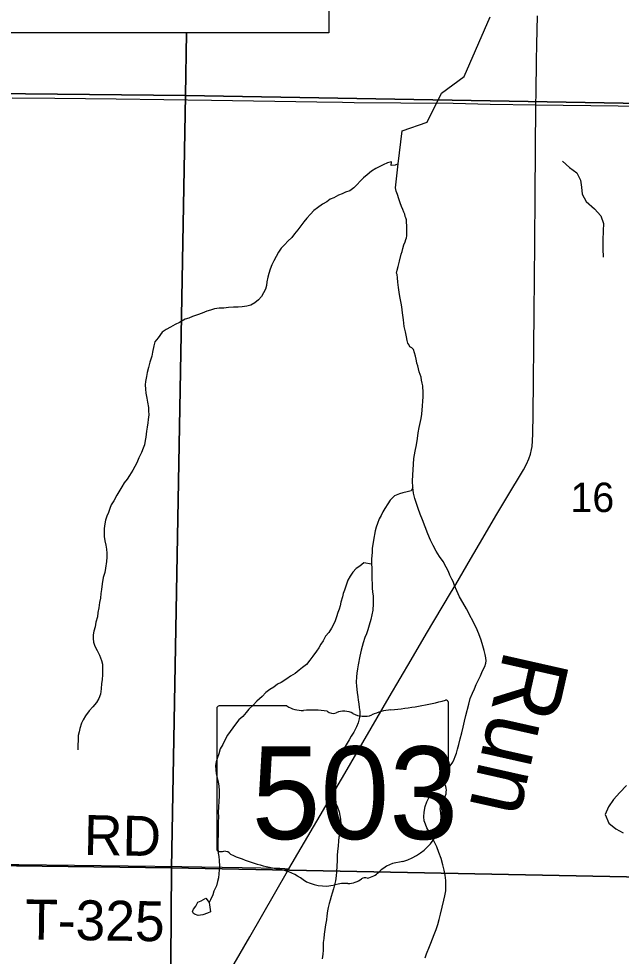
# Model space of a CAD drawing. Extents: x -8.8 to 41.4, y 0 to 34.6.
# Drawn here: x 7.113 to 7.971, y 15.304 to 16.638 of the extents above; entities that cross this region are included whole.
import ezdxf

# ---------------------------------------------------------------- set-up
doc = ezdxf.new("R2010")
doc.units = 0
for name, color, linetype in [('GM_X_City_Street', 7, 'Continuous'), ('GM_X_Corporation', 7, 'Continuous'), ('GM_X_County_Road', 7, 'Continuous'), ('GM_X_Minor_River', 7, 'Continuous'), ('GM_X_Minor_River_Text', 7, 'Continuous'), ('GM_X_Section_Text', 7, 'Continuous'), ('GM_X_State_Route', 7, 'Continuous'), ('GM_X_Township_Road', 7, 'Continuous'), ('GM_X_Township_Text', 7, 'Continuous'), ('GM_X_Unincorporated_Location', 7, 'Continuous'), ('SH_Data', 7, 'Continuous')]:
    doc.layers.add(name, color=color, linetype=linetype)

msp = doc.modelspace()

# ---------------------------------------------------------------- linework, layer by layer
at = {"layer": 'GM_X_City_Street'}
for p, q in [((7.4951, 15.6598), (7.3986, 15.6598)), ((7.725, 15.5601), (7.725, 15.6648)), ((7.3954, 15.6564), (7.3954, 15.4563)), ((7.7249, 15.5601), (7.725, 15.5601))]:
    msp.add_line(p, q, dxfattribs=at)
for centre, major_axis, start_param, end_param in [((7.3992, 15.6568), (0.00382, 0), 1.712693, 3.28349), ((7.5181, 15.683), (0.037, 0), 4.042523, 4.731795), ((7.6076, 15.9326), (0.3495, 0), 4.814394, 5.042369), ((7.7213, 15.6652), (0.00367, 0), 6.141152, 7.989035), ((7.5304, 15.5475), (0.133, 0), 1.404758, 1.657858), ((7.5606, 15.6578), (0.0107, 0), 3.836095, 5.185415), ((7.5763, 15.6347), (0.0222, 0), 0.950623, 2.079405), ((7.6049, 15.6664), (0.0267, 0), 4.081561, 5.145723), ((7.6521, 15.5987), (0.0703, 0), 1.699011, 2.107814), ((7.7241, 15.5524), (0.00568, 0), 1.883978, 3.671073), ((7.721, 15.5597), (0.00393, 0), 5.05454, 6.418171), ((7.688, 15.5392), (0.0341, 0), 5.934695, 6.695948), ((7.7381, 15.5163), (0.0248, 0), 2.387724, 3.262537), ((7.6271, 15.503), (0.0874, 0), 5.101752, 6.440018), ((7.3992, 15.4558), (0.00385, 0), 3.00124, 4.508301), ((7.3998, 15.4763), (0.0294, 0), 4.665946, 4.897461), ((7.4058, 15.4447), (0.0106, 0), 0.519207, 1.627899), ((7.5396, 15.6245), (0.2524, 0), 4.195997, 4.488961), ((7.664, 15.4001), (0.0479, 0), 1.647645, 2.488434), ((7.4644, 15.3663), (0.079, 0), 0.823519, 1.323587), ((7.6033, 15.4369), (0.0282, 0), 4.937069, 5.64225), ((7.5498, 15.4437), (0.0501, 0), 4.026481, 4.996735), ((7.5787, 15.3745), (0.0412, 0), 1.495662, 1.94098), ((7.5824, 15.4287), (0.0267, 0), 4.691044, 5.507374), ((7.6065, 15.4093), (0.00752, 0), 1.147584, 2.315152)]:
    msp.add_ellipse(centre, major_axis=major_axis, ratio=0.8, start_param=start_param, end_param=end_param, dxfattribs=at)
at = {"layer": 'GM_X_Corporation'}
for points in [[(7.3578, 17.0515), (7.3641, 17.5315), (8.3581, 17.5144), (8.3533, 16.5107), (7.351, 16.5283), (7.3522, 16.6176)], [(7.3522, 16.6176), (7.351, 16.5283), (6.3489, 16.539), (6.3498, 16.6176)]]:
    msp.add_lwpolyline(points, dxfattribs=at)
for points in [[(6.3489, 16.539), (7.351, 16.5283), (7.3307, 15.4293), (6.3374, 15.4422)], [(7.351, 16.5283), (8.3533, 16.5107), (8.3386, 15.4097), (7.3307, 15.4293)], [(6.3374, 15.4422), (7.3307, 15.4293), (7.3236, 14.4245), (6.336, 14.4395)], [(7.3307, 15.4293), (8.3386, 15.4097), (8.3298, 14.411), (7.3236, 14.4245)]]:
    msp.add_lwpolyline(points, close=True, dxfattribs=at)
at = {"layer": 'GM_X_County_Road'}
for points in [[(7.1041, 16.5251), (7.1649, 16.5244), (7.2519, 16.5234), (7.3879, 16.5217), (7.5376, 16.5191), (7.5743, 16.5187), (7.5911, 16.5184), (7.6574, 16.5178), (7.7319, 16.5174), (7.7846, 16.516), (7.8496, 16.5151)], [(7.8496, 16.5151), (8.084, 16.5124), (8.3525, 16.5093), (8.5865, 16.5068), (8.7909, 16.5044), (8.9, 16.5027)]]:
    msp.add_lwpolyline(points, dxfattribs=at)
at = {"layer": 'GM_X_Minor_River'}
for points in [[(7.6536, 16.431), (7.659, 16.4782), (7.695, 16.4906), (7.7154, 16.5317), (7.7473, 16.5553), (7.7844, 16.6404)], [(7.6536, 16.431), (7.6493, 16.4291), (7.6436, 16.4289), (7.6441, 16.4338), (7.6384, 16.4324)], [(7.8873, 16.4349), (7.8973, 16.4259), (7.9077, 16.4184), (7.9131, 16.4079), (7.9147, 16.398), (7.9152, 16.3881), (7.921, 16.3773), (7.9328, 16.3671), (7.942, 16.357), (7.9459, 16.3462), (7.9452, 16.3356), (7.9448, 16.3223), (7.9449, 16.3102), (7.9453, 16.2984)], [(7.6384, 16.4324), (7.6322, 16.4299), (7.6272, 16.4274), (7.6218, 16.4245), (7.6156, 16.4205), (7.6094, 16.4154), (7.6044, 16.4113), (7.5903, 16.3969), (7.5845, 16.3929), (7.5787, 16.3908), (7.5738, 16.3886), (7.5684, 16.3865), (7.5618, 16.3829), (7.5568, 16.3808), (7.5518, 16.3771), (7.5456, 16.3735), (7.5387, 16.3687), (7.5336, 16.3647), (7.5285, 16.3595), (7.5234, 16.354), (7.5191, 16.3488), (7.5148, 16.3428), (7.5108, 16.3372), (7.5061, 16.3317), (7.5022, 16.3265), (7.4967, 16.3213), (7.4924, 16.3165), (7.4869, 16.3113), (7.483, 16.3053), (7.4798, 16.2993), (7.4766, 16.293), (7.4737, 16.2874), (7.4713, 16.2813), (7.4692, 16.2753), (7.4679, 16.2697), (7.4666, 16.2632), (7.4661, 16.2579), (7.4648, 16.2527), (7.462, 16.2474), (7.4592, 16.2426), (7.4549, 16.2377), (7.4494, 16.2333), (7.4437, 16.2301), (7.4383, 16.2287), (7.4315, 16.2278), (7.4257, 16.2272), (7.4193, 16.227), (7.4121, 16.2268), (7.4052, 16.2258), (7.3988, 16.2256), (7.3923, 16.2247), (7.3865, 16.2229), (7.3812, 16.2216), (7.3743, 16.2187), (7.3678, 16.2163), (7.3609, 16.2138), (7.3555, 16.2117), (7.3501, 16.2099), (7.3424, 16.2056), (7.3359, 16.2027), (7.3293, 16.1987), (7.3235, 16.1955), (7.3177, 16.1915), (7.3118, 16.1836), (7.3071, 16.1781), (7.3058, 16.1724), (7.304, 16.163), (7.3027, 16.1573), (7.3002, 16.149), (7.2981, 16.1415), (7.2964, 16.1343), (7.2951, 16.1286), (7.2941, 16.1214), (7.2936, 16.1165), (7.2938, 16.1104), (7.2944, 16.1047), (7.2957, 16.0975), (7.2967, 16.0921), (7.298, 16.0845), (7.2982, 16.0795), (7.2985, 16.0742), (7.2979, 16.0674), (7.297, 16.0625), (7.2961, 16.0564), (7.2955, 16.0507), (7.2945, 16.0424), (7.2936, 16.0375), (7.2923, 16.0314), (7.2907, 16.0265), (7.2882, 16.0205), (7.2846, 16.0127), (7.2813, 16.0055), (7.2785, 16.0003), (7.2757, 15.9954), (7.2713, 15.9876), (7.2678, 15.9824), (7.2635, 15.9772), (7.2603, 15.9715), (7.2531, 15.9596), (7.2487, 15.9517), (7.2451, 15.9458)], [(7.6497, 16.3972), (7.6536, 16.431)], [(7.7685, 15.7625), (7.7646, 15.7713), (7.7507, 15.7979), (7.7456, 15.8068), (7.741, 15.8153), (7.7371, 15.8234), (7.7339, 15.8311), (7.7318, 15.8369), (7.73, 15.8404), (7.7286, 15.8431), (7.7271, 15.8461), (7.725, 15.8512), (7.7218, 15.8573), (7.7175, 15.8651), (7.7124, 15.8724), (7.7077, 15.8802), (7.7034, 15.8879), (7.6995, 15.8956), (7.6956, 15.9045), (7.6921, 15.9148), (7.6883, 15.9244), (7.6847, 15.9325), (7.6819, 15.9406), (7.6795, 15.9479), (7.6771, 15.9548), (7.6754, 15.9624), (7.6745, 15.9708), (7.6737, 15.9803), (7.6758, 16.0118), (7.6776, 16.0224), (7.6794, 16.0315), (7.6808, 16.0405), (7.6822, 16.0485), (7.6836, 16.056), (7.6862, 16.0689), (7.6872, 16.0749), (7.6883, 16.087), (7.6885, 16.0935), (7.6891, 16.0995), (7.6889, 16.1052), (7.6884, 16.1151), (7.6878, 16.1189), (7.6868, 16.1232), (7.6861, 16.1274), (7.6848, 16.1316), (7.6834, 16.1354), (7.6813, 16.1438), (7.6803, 16.1473), (7.6797, 16.1507), (7.679, 16.153), (7.6783, 16.1576), (7.677, 16.1622), (7.6752, 16.1668), (7.673, 16.1692), (7.67, 16.1708), (7.6686, 16.1739), (7.6675, 16.1758), (7.6662, 16.18), (7.6652, 16.185), (7.6639, 16.1919), (7.6622, 16.1999), (7.661, 16.2094), (7.6598, 16.2193), (7.6589, 16.2277), (7.6579, 16.2331), (7.6569, 16.2376), (7.656, 16.2426), (7.655, 16.2483), (7.6541, 16.2552), (7.6532, 16.2628), (7.6526, 16.2689), (7.652, 16.2735), (7.6513, 16.2758), (7.6522, 16.28), (7.6535, 16.2852), (7.6547, 16.289), (7.6552, 16.2924), (7.6578, 16.3026), (7.659, 16.3063), (7.6603, 16.3105), (7.6616, 16.3158), (7.6636, 16.3203), (7.6645, 16.3233), (7.6653, 16.3259), (7.6658, 16.3289), (7.6659, 16.3339), (7.6657, 16.3388), (7.6659, 16.3434), (7.6656, 16.3475), (7.6653, 16.3513), (7.6643, 16.3544), (7.6636, 16.3563), (7.6629, 16.3594), (7.6615, 16.3625), (7.6601, 16.3663), (7.6583, 16.3702), (7.6562, 16.3756), (7.6545, 16.3813), (7.6524, 16.3874), (7.6507, 16.3924), (7.6497, 16.3972)], [(7.6745, 15.9708), (7.6722, 15.966), (7.6664, 15.9646), (7.6603, 15.9629), (7.6553, 15.9615), (7.6481, 15.9587), (7.6422, 15.9528), (7.6386, 15.9476), (7.6347, 15.9408), (7.6315, 15.936), (7.6291, 15.9307), (7.6266, 15.9259), (7.6242, 15.9195), (7.6221, 15.9142), (7.6208, 15.9089), (7.6186, 15.8957), (7.6167, 15.8836), (7.6166, 15.8786), (7.6155, 15.8688), (7.6157, 15.8616), (7.6159, 15.8562), (7.6158, 15.8513), (7.616, 15.846), (7.6158, 15.8395), (7.6164, 15.8338), (7.6166, 15.8277), (7.6172, 15.8216), (7.6178, 15.8163), (7.6181, 15.811), (7.6179, 15.8053), (7.6173, 15.7962), (7.6146, 15.7826), (7.6121, 15.7747), (7.6104, 15.7682), (7.6083, 15.7622), (7.6063, 15.7573), (7.6038, 15.7498), (7.6021, 15.7442), (7.6009, 15.7392), (7.5991, 15.7306), (7.5965, 15.7185), (7.5955, 15.7124), (7.5946, 15.7064), (7.5941, 15.7011), (7.5939, 15.6938), (7.5941, 15.6878), (7.5953, 15.679), (7.5959, 15.6729), (7.5966, 15.6679), (7.5975, 15.663), (7.5978, 15.6576), (7.5991, 15.6519), (7.599, 15.6462), (7.5981, 15.6413), (7.5964, 15.6356), (7.5943, 15.63), (7.5903, 15.6225), (7.5868, 15.6169), (7.5836, 15.6117), (7.578, 15.602), (7.5744, 15.596), (7.5715, 15.5888), (7.5699, 15.5839), (7.5686, 15.5771), (7.5672, 15.5707), (7.5663, 15.5658), (7.5643, 15.5594), (7.5626, 15.5538), (7.5609, 15.5485), (7.5604, 15.5432), (7.5598, 15.5371), (7.5604, 15.5314), (7.5618, 15.5264), (7.5647, 15.521), (7.5672, 15.5156), (7.5693, 15.5091), (7.5707, 15.5041), (7.5716, 15.4988), (7.5718, 15.4916), (7.5713, 15.4851), (7.5703, 15.4779), (7.569, 15.473), (7.5685, 15.4681)], [(7.2451, 15.9458), (7.2431, 15.9409), (7.241, 15.9352), (7.2386, 15.9296), (7.2369, 15.924), (7.236, 15.9187), (7.2351, 15.9122), (7.2349, 15.9069), (7.2351, 15.9008), (7.2361, 15.8947), (7.2374, 15.8886), (7.2384, 15.8829), (7.239, 15.8772), (7.2388, 15.8715), (7.2383, 15.8654), (7.2369, 15.8559), (7.2359, 15.8499), (7.2338, 15.8427), (7.2324, 15.8336), (7.2311, 15.8257), (7.2301, 15.8196), (7.2296, 15.8132), (7.2283, 15.8072), (7.2273, 15.7996), (7.226, 15.7928), (7.2254, 15.7867), (7.2233, 15.7792), (7.222, 15.7724), (7.2203, 15.7663), (7.2194, 15.7611), (7.2192, 15.7557), (7.2198, 15.7508), (7.2216, 15.745), (7.2252, 15.7389), (7.2284, 15.7323), (7.2312, 15.7246), (7.2326, 15.7193), (7.2325, 15.7143), (7.2327, 15.7094), (7.2326, 15.7044), (7.232, 15.6969), (7.2314, 15.6916), (7.2309, 15.6844), (7.2299, 15.6768), (7.2274, 15.6704), (7.2242, 15.6648), (7.2191, 15.6585), (7.2137, 15.6529), (7.2085, 15.6458), (7.2053, 15.6402), (7.2029, 15.6354), (7.2004, 15.6278), (7.1995, 15.6229), (7.1982, 15.618), (7.1977, 15.5975)], [(7.6157, 15.8616), (7.6048, 15.8634), (7.5989, 15.8586), (7.5939, 15.8553), (7.5892, 15.8502), (7.5853, 15.8446), (7.582, 15.8386), (7.58, 15.8329), (7.5771, 15.8247), (7.5754, 15.8198), (7.5742, 15.8149), (7.5721, 15.8077), (7.5708, 15.8024), (7.5695, 15.7975), (7.5678, 15.7926), (7.5658, 15.7866), (7.5637, 15.781), (7.5613, 15.7757), (7.5585, 15.7705), (7.5549, 15.7641), (7.5502, 15.7593), (7.5466, 15.7526), (7.5434, 15.7477), (7.5406, 15.7425), (7.5374, 15.7376), (7.5319, 15.7306), (7.5276, 15.725), (7.5229, 15.719), (7.5174, 15.7146), (7.5124, 15.7106), (7.507, 15.7062), (7.5004, 15.7022), (7.495, 15.6985), (7.4872, 15.6934), (7.4819, 15.6909), (7.4764, 15.6865), (7.471, 15.6833), (7.4652, 15.6789), (7.4597, 15.6733), (7.4523, 15.6667), (7.4469, 15.6608), (7.441, 15.6552), (7.4371, 15.6504), (7.4324, 15.6448), (7.4269, 15.64), (7.4218, 15.6341), (7.4182, 15.6285), (7.4143, 15.6237), (7.4107, 15.6181), (7.4079, 15.6132), (7.4039, 15.605)], [(7.6919, 15.3014), (7.694, 15.307), (7.6981, 15.3175), (7.7001, 15.3224), (7.7047, 15.3348), (7.7075, 15.3419), (7.71, 15.349), (7.7121, 15.3562), (7.7139, 15.3634), (7.7187, 15.3834), (7.72, 15.3898), (7.7213, 15.3966), (7.7215, 15.4038), (7.7214, 15.4114), (7.7205, 15.419), (7.7188, 15.4263), (7.7172, 15.4339), (7.7148, 15.4427), (7.7116, 15.4512), (7.7085, 15.4593), (7.7053, 15.4662), (7.7024, 15.4716), (7.6974, 15.4816), (7.6945, 15.4863), (7.6924, 15.4917), (7.6907, 15.4963), (7.6901, 15.502), (7.6907, 15.5088), (7.692, 15.5167), (7.6945, 15.5235), (7.697, 15.5291), (7.6998, 15.5351), (7.703, 15.5407), (7.7066, 15.5459), (7.7102, 15.5515), (7.7141, 15.5563), (7.718, 15.5604), (7.7212, 15.5645), (7.7243, 15.5689), (7.7275, 15.5745), (7.7311, 15.5797), (7.7331, 15.5842), (7.7348, 15.588), (7.7364, 15.5925), (7.7381, 15.5981), (7.7398, 15.6049), (7.742, 15.6128), (7.7441, 15.6215), (7.7459, 15.6298), (7.748, 15.6381), (7.7498, 15.6464), (7.7541, 15.6622), (7.7562, 15.6705), (7.7591, 15.678), (7.762, 15.6844), (7.7644, 15.6904), (7.7677, 15.6968), (7.7705, 15.7028), (7.7737, 15.7099), (7.7769, 15.7159), (7.7782, 15.7208), (7.7787, 15.7242), (7.7785, 15.7283), (7.7775, 15.7329), (7.7758, 15.7387), (7.7741, 15.7452), (7.7717, 15.7536), (7.7685, 15.7625)], [(7.4039, 15.605), (7.4003, 15.5986), (7.3982, 15.5918), (7.3962, 15.5866), (7.3945, 15.5805), (7.3936, 15.5752), (7.3942, 15.5688), (7.3944, 15.5634), (7.3961, 15.5577), (7.3975, 15.552), (7.3981, 15.5459), (7.3986, 15.5394), (7.3988, 15.531), (7.3982, 15.5246), (7.3976, 15.5155), (7.3974, 15.509), (7.3976, 15.5018), (7.3974, 15.495), (7.3975, 15.4866), (7.3967, 15.4585), (7.3972, 15.4505), (7.3982, 15.4455), (7.3988, 15.4398), (7.399, 15.4318), (7.3985, 15.4265), (7.3983, 15.4208), (7.3978, 15.4152), (7.3965, 15.4099), (7.3948, 15.4038), (7.3912, 15.3963), (7.3895, 15.3911), (7.3863, 15.3839), (7.3843, 15.3801)], [(7.9786, 15.5466), (7.9692, 15.5366), (7.9602, 15.5266), (7.9527, 15.5162), (7.9482, 15.5056), (7.9532, 15.493), (7.9632, 15.4851), (7.974, 15.4795)], [(7.5685, 15.4681), (7.5679, 15.4605), (7.5673, 15.4533), (7.5668, 15.4469), (7.5666, 15.44), (7.5663, 15.4321), (7.5657, 15.4237), (7.5652, 15.418), (7.5642, 15.4112), (7.5629, 15.4052), (7.5616, 15.3995), (7.5595, 15.3935), (7.5583, 15.3886), (7.5566, 15.3837), (7.5553, 15.3788), (7.554, 15.3731), (7.5531, 15.3682), (7.5522, 15.3614), (7.5513, 15.3553), (7.5499, 15.3485), (7.5493, 15.3417), (7.548, 15.3349), (7.5475, 15.3288), (7.5469, 15.3232), (7.5466, 15.3122), (7.5461, 15.3068), (7.5455, 15.3)], [(7.3843, 15.3801), (7.3866, 15.3671), (7.382, 15.365), (7.3755, 15.3625), (7.3686, 15.3619), (7.3637, 15.3636), (7.3622, 15.3644), (7.3608, 15.3675), (7.3624, 15.3709), (7.3656, 15.375), (7.3684, 15.3806), (7.373, 15.3827)], [(7.373, 15.3827), (7.3798, 15.3864), (7.3843, 15.3801)]]:
    msp.add_lwpolyline(points, dxfattribs=at)
at = {"layer": 'GM_X_State_Route'}
msp.add_lwpolyline([(7.3753, 15.216), (7.4423, 15.3315), (7.4959, 15.4246), (7.498, 15.4283), (7.5776, 15.5638), (7.6408, 15.6722), (7.6719, 15.7253), (7.6939, 15.7628), (7.7282, 15.8204), (7.7355, 15.8327), (7.7564, 15.8686), (7.7739, 15.8987), (7.7924, 15.9303), (7.8083, 15.9563), (7.832, 15.9957), (7.8364, 16.004), (7.8396, 16.0115), (7.8418, 16.018), (7.8433, 16.0245), (7.8441, 16.0291), (7.8449, 16.0372), (7.8453, 16.0472), (7.8455, 16.0751), (7.8469, 16.2193), (7.8481, 16.318), (7.8486, 16.387), (7.8496, 16.5151), (7.8499, 16.5319), (7.8506, 16.578), (7.8509, 16.601), (7.8517, 16.6419)], dxfattribs=at)
at = {"layer": 'GM_X_Township_Road'}
msp.add_lwpolyline([(6.7304, 15.4382), (6.7677, 15.4379), (6.8577, 15.4363), (6.9309, 15.4356), (7.0122, 15.4344), (7.0557, 15.4342), (7.1134, 15.4342), (7.1929, 15.4335), (7.3457, 15.4315), (7.4313, 15.43), (7.4853, 15.429), (7.4921, 15.4286), (7.498, 15.4283)], dxfattribs=at)
at = {"layer": 'SH_Data'}
msp.add_lwpolyline([(5.4782, 17.0515), (7.5548, 17.0515), (7.5548, 16.6176), (5.4782, 16.6176)], close=True, dxfattribs=at)

# ---------------------------------------------------------------- texts
at = {"layer": 'GM_X_City_Street'}
msp.add_text('503', height=0.13184, dxfattribs=at).set_placement((7.4448, 15.4704))
at = {"layer": 'GM_X_Minor_River_Text'}
msp.add_text('Run', height=0.09466, rotation=257.2923, dxfattribs=at).set_placement((7.8054, 15.7423))
at = {"layer": 'GM_X_Section_Text'}
for s, rotation, p in [('RD', 359.0128, (7.2058, 15.4479)), ('T-325', 359.1574, (7.1223, 15.3278))]:
    msp.add_text(s, height=0.05682, rotation=rotation, dxfattribs=at).set_placement(p)
at = {"layer": 'GM_X_Township_Text'}
msp.add_text('16', height=0.04186, rotation=0, dxfattribs=at).set_placement((7.8988, 15.9357))
at = {"layer": 'GM_X_Unincorporated_Location'}
for s in ['s', 'r']:
    msp.add_text(s, height=0.000189, dxfattribs=at).set_placement((7.5565, 15.543))
msp.add_text('503', height=0.000189, rotation=0, dxfattribs=at).set_placement((7.4896, 15.5292))

doc.saveas('drawing.dxf')
